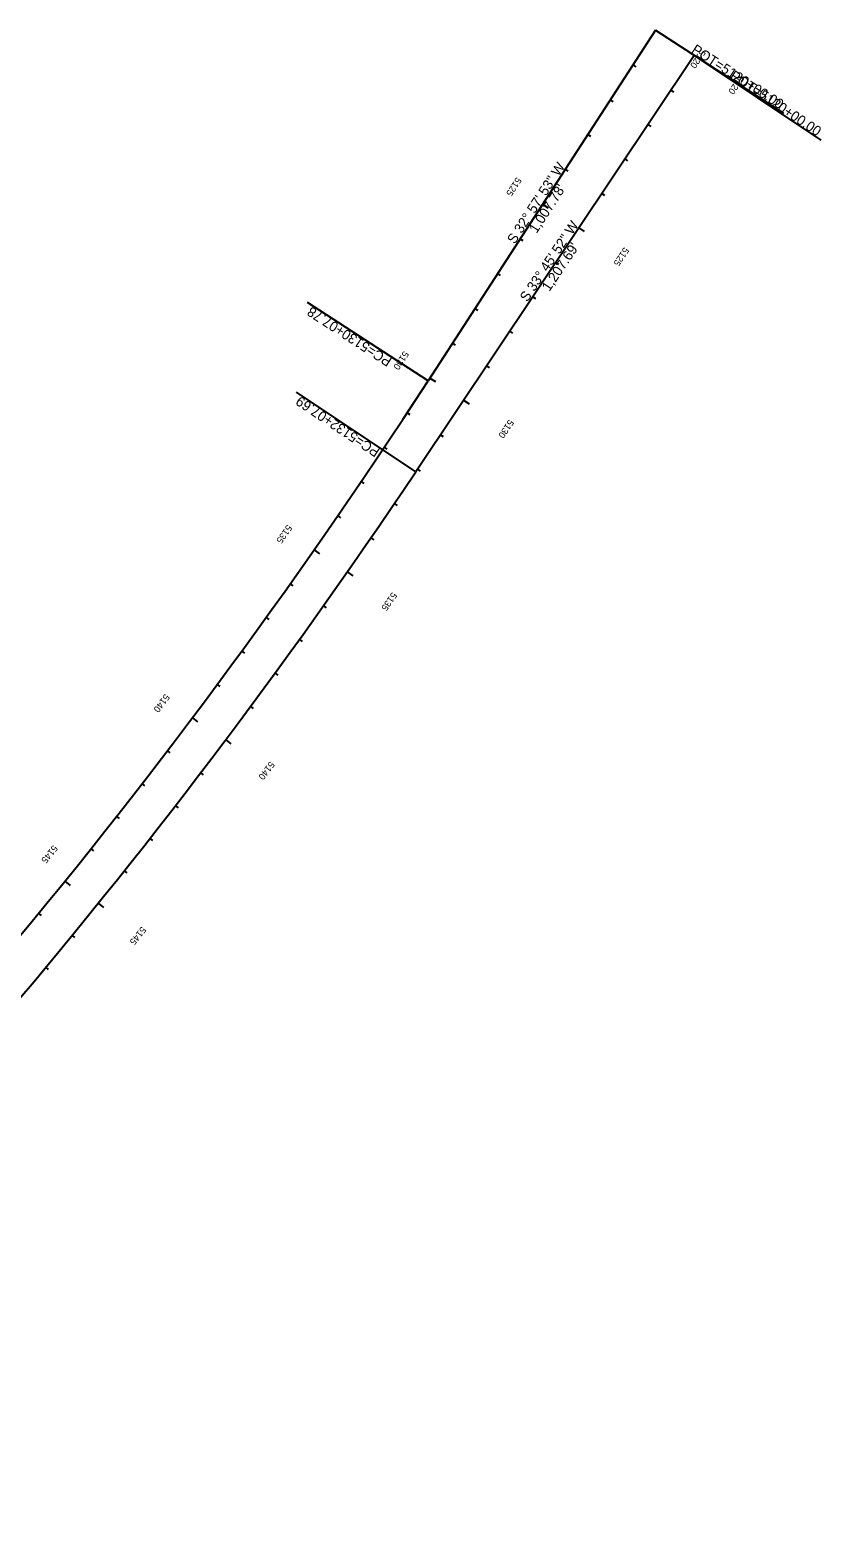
# Model space of a CAD drawing. Extents: x 2160877 to 2175861, y 601747 to 617724.
# Drawn here: x 2173955 to 2175861, y 614087 to 617724 of the extents above; entities that cross this region are included whole.
import ezdxf

# ---------------------------------------------------------------- set-up
doc = ezdxf.new("R2010")
doc.units = 0
for name, color, linetype in [('RD_HC_Cl', 7, 'Continuous'), ('RD_HC_Data', 7, 'Continuous'), ('RD_HC_Data_Tic', 7, 'Continuous'), ('RD_HC_TX_StaOther', 7, 'Continuous')]:
    doc.layers.add(name, color=color, linetype=linetype)

msp = doc.modelspace()

# ---------------------------------------------------------------- linework, layer by layer
at = {"layer": 'RD_HC_Cl'}
for p, q in [((2175462.5, 617723.5), (2174914.1, 616878)), ((2175555.6, 617662.2), (2174884.4, 616658.2))]:
    msp.add_line(p, q, dxfattribs=at)
for radius, end in [(14276, 327.03525), (14372, 326.23563)]:
    msp.add_arc((2162936.5, 624645.9), radius, 312.71947, end, dxfattribs=at)
at = {"layer": 'RD_HC_Data'}
for p, q in [((2175462.5, 617723.5), (2175770.9, 617523.5)), ((2175555.6, 617662.2), (2175861.2, 617457.9)), ((2174914.1, 616878), (2174623.8, 617066.3)), ((2174884.4, 616658.2), (2174596.7, 616850.5))]:
    msp.add_line(p, q, dxfattribs=at)
at = {"layer": 'RD_HC_Data_Tic'}
for p, q in [((2175462.5, 617723.5), (2175475.9, 617714.8)), ((2175555.6, 617662.2), (2175568.9, 617653.3)), ((2175408.1, 617639.6), (2175414.8, 617635.3)), ((2175353.7, 617555.7), (2175360.4, 617551.4)), ((2175500, 617579.1), (2175506.6, 617574.7)), ((2175444.4, 617496), (2175451.1, 617491.5)), ((2175299.2, 617471.8), (2175306, 617467.5)), ((2175388.8, 617412.8), (2175395.5, 617408.4)), ((2175244.8, 617387.9), (2175251.5, 617383.6)), ((2175190.4, 617304), (2175203.8, 617295.3)), ((2175333.3, 617329.7), (2175339.9, 617325.3)), ((2175277.7, 617246.6), (2175291, 617237.7)), ((2175136, 617220.1), (2175142.7, 617215.8)), ((2175222.1, 617163.4), (2175228.8, 617159)), ((2175081.6, 617136.2), (2175088.3, 617131.9)), ((2175166.5, 617080.3), (2175173.2, 617075.9)), ((2175027.2, 617052.3), (2175033.9, 617048)), ((2175110.9, 616997.2), (2175117.6, 616992.7)), ((2174972.8, 616968.4), (2174979.5, 616964.1)), ((2175055.4, 616914), (2175062, 616909.6)), ((2174918.4, 616884.5), (2174931.8, 616875.8)), ((2174999.8, 616830.9), (2175013.1, 616822)), ((2174863.7, 616800.8), (2174870.4, 616796.4)), ((2174808.5, 616717.4), (2174815.1, 616713)), ((2174944.2, 616747.8), (2174950.9, 616743.3)), ((2174888.6, 616664.6), (2174895.3, 616660.2)), ((2174752.6, 616634.5), (2174759.2, 616630)), ((2174832.8, 616581.7), (2174839.4, 616577.2)), ((2174696.2, 616551.9), (2174702.8, 616547.4)), ((2174776.4, 616499.1), (2174783, 616494.6)), ((2174639.2, 616469.7), (2174652.3, 616460.6)), ((2174581.7, 616387.9), (2174588.2, 616383.3)), ((2174719.4, 616416.9), (2174732.6, 616407.7)), ((2174661.9, 616335.1), (2174668.4, 616330.5)), ((2174523.5, 616306.6), (2174530, 616301.9)), ((2174603.8, 616253.7), (2174610.3, 616249.1)), ((2174464.8, 616225.6), (2174471.3, 616220.9)), ((2174545.1, 616172.8), (2174551.6, 616168)), ((2174405.6, 616145.1), (2174412, 616140.3)), ((2174345.8, 616064.9), (2174358.5, 616055.3)), ((2174485.9, 616092.2), (2174492.3, 616087.4)), ((2174426.1, 616012), (2174438.9, 616002.4)), ((2174285.4, 615985.2), (2174291.7, 615980.4)), ((2174365.7, 615932.3), (2174372.1, 615927.5)), ((2174224.4, 615906), (2174230.7, 615901.1)), ((2174304.8, 615853), (2174311.2, 615848.1)), ((2174162.9, 615827.1), (2174169.2, 615822.2)), ((2174243.4, 615774.1), (2174249.7, 615769.2)), ((2174100.9, 615748.7), (2174107.1, 615743.7)), ((2174038.3, 615670.7), (2174050.7, 615660.6)), ((2174181.4, 615695.7), (2174187.6, 615690.7)), ((2173975.1, 615593.2), (2173981.3, 615588.1)), ((2174118.8, 615617.6), (2174131.3, 615607.6)), ((2174055.7, 615540), (2174061.9, 615535)), ((2173992.1, 615462.9), (2173998.3, 615457.8))]:
    msp.add_line(p, q, dxfattribs=at)

# ---------------------------------------------------------------- texts
at = {"layer": 'RD_HC_Data'}
for s, rotation, p in [('POT=5120+00.00', 327.0352, (2175547.5, 617670.8)), ('POT=5120+00.00', 326.2356, (2175639.8, 617608.3)), ('PC=5130+07.78', 147.0352, (2174829.1, 616930.7)), ('PC=5132+07.69', 146.2356, (2174800.1, 616712.2))]:
    msp.add_text(s, height=24, rotation=rotation, dxfattribs=at).set_placement(p)
at = {"layer": 'RD_HC_TX_StaOther'}
for s, height, rotation, p in [('5120', 16, 237.0352, (2175571.3, 617678.1)), ('5120', 16, 236.2356, (2175663.7, 617615.3)), ('S 32%%d 57\' 53" W', 24, 57.0352, (2175123.3, 617206)), ('5125', 16, 237.0352, (2175127.4, 617369.9)), ("1,007.78'", 24, 57.0352, (2175175.9, 617232)), ('S 33%%d 45\' 52" W', 24, 56.2356, (2175153.6, 617066.4)), ("1,207.69'", 24, 56.2356, (2175206.6, 617091.6)), ('5125', 16, 236.2356, (2175386.8, 617201.1)), ('5130', 16, 237.0352, (2174855.6, 616950.8)), ('5130', 16, 236.2356, (2175109.2, 616785.8)), ('5135', 16, 235.0597, (2174574.6, 616531.9)), ('5135', 16, 235.0703, (2174827.6, 616369.2)), ('5140', 16, 233.053, (2174279.7, 616123.7)), ('5140', 16, 233.077, (2174532.8, 615961)), ('5145', 16, 231.0463, (2174010.2, 615759.2)), ('5145', 16, 231.0836, (2174223.4, 615562.5))]:
    msp.add_text(s, height=height, rotation=rotation, dxfattribs=at).set_placement(p)

doc.saveas('drawing.dxf')
